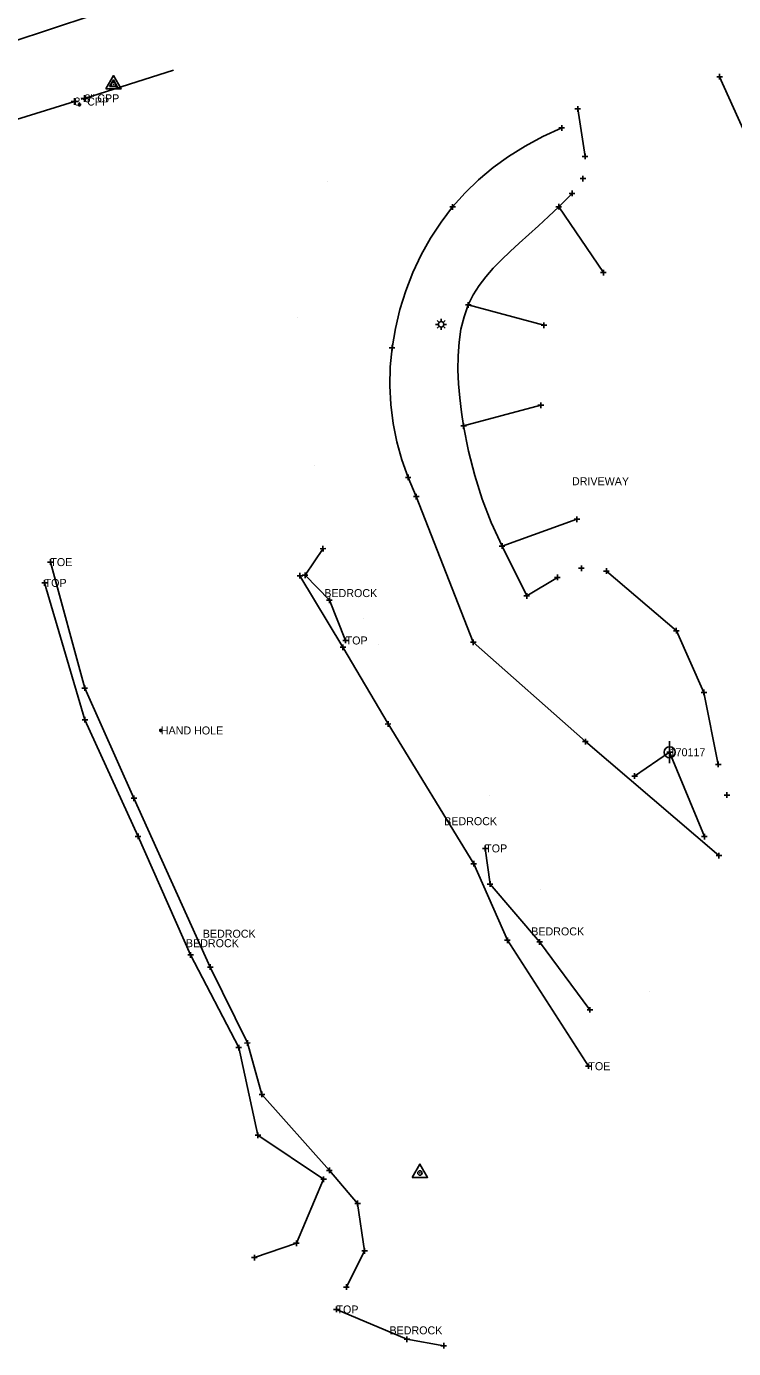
# Model space of a CAD drawing. Extents: x 1729655 to 1739338, y 463812 to 469501.
# Drawn here: x 1735905.4 to 1736064.5, y 466814.8 to 467112.2 of the extents above; entities that cross this region are included whole.
import ezdxf

# ---------------------------------------------------------------- set-up
doc = ezdxf.new("R2010")
doc.units = 0
for name, color, linetype in [('Default', 7, 'Continuous'), ('S_Bridge_Column_Round', 7, 'Continuous'), ('S_Bridge_Deck', 7, 'Continuous'), ('S_Bridge_ExpansionJoint', 7, 'Continuous'), ('S_Buildings', 7, 'Continuous'), ('S_Buildings_Steps', 7, 'Continuous'), ('S_Control_Temp_Traverse', 7, 'Continuous'), ('S_Drainage_Sump', 7, 'Continuous'), ('S_Ground_SpotElevation', 7, 'Continuous'), ('S_RetWall_Top', 7, 'Continuous'), ('S_Roadway_Bedrock_Outcrop', 7, 'Continuous'), ('S_Roadway_Drive_Gravel', 7, 'Continuous'), ('S_Survey_Shot', 7, 'Continuous'), ('S_Terrain_Boundary', 7, 'Continuous'), ('S_Terrain_High_Points', 7, 'Continuous'), ('S_Terrain_Imported_Contours', 7, 'Continuous'), ('S_Trees_TreeLine', 7, 'Continuous'), ('S_Utilities_AG_Communications', 7, 'Continuous')]:
    doc.layers.add(name, color=color, linetype=linetype)

msp = doc.modelspace()

# ---------------------------------------------------------------- linework, layer by layer
at = {"layer": 'Default'}
for p, q in [((1735973.06, 467077.39), (1735973.06, 467077.39)), ((1735966.26, 467046.77), (1735966.26, 467046.77)), ((1735970.29, 467013.47), (1735970.29, 467013.47)), ((1735981.31, 466979.09), (1735981.31, 466979.09)), ((1735984.57, 466973.07), (1735984.57, 466973.07)), ((1736009.54, 466939.2), (1736009.54, 466939.2)), ((1736021.02, 466918.08), (1736021.02, 466918.08)), ((1736045.63, 466895.05), (1736045.63, 466895.05))]:
    msp.add_line(p, q, dxfattribs=at)
at = {"layer": 'S_Bridge_Column_Round'}
for p, q in [((1736060.7, 467100.89), (1736061.97, 467100.89)), ((1736061.34, 467100.26), (1736061.33, 467101.53)), ((1736061.34, 467100.89), (1736061.34, 467100.89)), ((1736028.79, 467093.66), (1736030.07, 467093.66)), ((1736029.43, 467093.03), (1736029.43, 467094.3)), ((1736029.43, 467093.66), (1736029.43, 467093.66)), ((1736025.17, 467089.38), (1736026.44, 467089.38)), ((1736025.17, 467089.38), (1736026.44, 467089.38)), ((1736025.81, 467088.74), (1736025.81, 467090.02)), ((1736025.81, 467088.74), (1736025.81, 467090.02)), ((1736025.81, 467089.38), (1736025.81, 467089.38)), ((1736025.81, 467089.38), (1736025.81, 467089.38)), ((1736030.43, 467082.96), (1736031.71, 467082.97)), ((1736031.07, 467082.33), (1736031.07, 467083.6)), ((1736031.07, 467082.96), (1736031.07, 467082.96)), ((1736029.94, 467077.98), (1736031.21, 467077.99)), ((1736030.58, 467077.35), (1736030.57, 467078.62)), ((1736030.57, 467077.99), (1736030.57, 467077.99)), ((1736027.5, 467074.65), (1736028.77, 467074.65)), ((1736028.14, 467074.01), (1736028.14, 467075.28)), ((1736028.14, 467074.65), (1736028.14, 467074.65)), ((1736000.63, 467071.59), (1736001.9, 467071.6)), ((1736001.27, 467070.96), (1736001.27, 467072.23)), ((1736001.27, 467071.6), (1736001.27, 467071.6)), ((1736024.51, 467071.64), (1736025.78, 467071.65)), ((1736024.51, 467071.64), (1736025.78, 467071.65)), ((1736025.15, 467071.01), (1736025.14, 467072.28)), ((1736025.15, 467071.01), (1736025.14, 467072.28)), ((1736025.14, 467071.64), (1736025.14, 467071.64)), ((1736025.14, 467071.64), (1736025.14, 467071.64)), ((1736034.57, 467056.84), (1736035.84, 467056.85)), ((1736035.21, 467056.21), (1736035.21, 467057.48)), ((1736035.21, 467056.85), (1736035.21, 467056.85)), ((1736004.79, 467048.93), (1736004.79, 467050.2)), ((1736004.79, 467048.93), (1736004.79, 467050.2)), ((1736004.16, 467049.56), (1736005.43, 467049.56)), ((1736004.16, 467049.56), (1736005.43, 467049.56)), ((1736004.79, 467049.56), (1736004.79, 467049.56)), ((1736004.79, 467049.56), (1736004.79, 467049.56)), ((1736021.18, 467044.98), (1736022.45, 467044.98)), ((1736021.81, 467044.34), (1736021.81, 467045.62)), ((1736021.81, 467044.98), (1736021.81, 467044.98)), ((1735987.02, 467039.93), (1735988.29, 467039.93)), ((1735987.66, 467039.3), (1735987.65, 467040.57)), ((1735987.65, 467039.93), (1735987.65, 467039.93)), ((1736020.48, 467026.99), (1736021.76, 467026.99)), ((1736021.12, 467026.35), (1736021.12, 467027.63)), ((1736021.12, 467026.99), (1736021.12, 467026.99)), ((1736003.11, 467022.35), (1736004.38, 467022.36)), ((1736003.11, 467022.35), (1736004.38, 467022.36)), ((1736003.75, 467021.72), (1736003.74, 467022.99)), ((1736003.75, 467021.72), (1736003.74, 467022.99)), ((1736003.74, 467022.35), (1736003.74, 467022.35)), ((1736003.74, 467022.35), (1736003.74, 467022.35)), ((1735991.27, 467010.14), (1735991.27, 467011.41)), ((1735990.63, 467010.77), (1735991.9, 467010.77)), ((1735991.27, 467010.77), (1735991.27, 467010.77)), ((1735992.46, 467006.43), (1735993.73, 467006.43)), ((1735993.1, 467005.79), (1735993.1, 467007.06)), ((1735993.1, 467006.43), (1735993.1, 467006.43)), ((1736028.61, 467001.35), (1736029.88, 467001.35)), ((1736029.25, 467000.71), (1736029.25, 467001.98)), ((1736029.25, 467001.35), (1736029.25, 467001.35)), ((1735971.47, 466994.73), (1735972.74, 466994.74)), ((1735972.11, 466994.1), (1735972.1, 466995.37)), ((1735972.11, 466994.74), (1735972.11, 466994.74)), ((1736011.78, 466995.3), (1736013.05, 466995.31)), ((1736011.78, 466995.3), (1736013.05, 466995.31)), ((1736012.41, 466994.67), (1736012.41, 466995.94)), ((1736012.41, 466994.67), (1736012.41, 466995.94)), ((1736012.41, 466995.3), (1736012.41, 466995.3)), ((1736012.41, 466995.3), (1736012.41, 466995.3)), ((1735910.11, 466991.71), (1735911.38, 466991.72)), ((1735910.75, 466991.08), (1735910.75, 466992.35)), ((1735910.75, 466991.71), (1735910.75, 466991.71)), ((1736030.25, 466989.69), (1736030.24, 466990.96)), ((1735909.46, 466986.39), (1735909.45, 466987.67)), ((1735909.46, 466986.39), (1735909.45, 466987.67)), ((1735966.28, 466988.64), (1735967.55, 466988.64)), ((1735966.28, 466988.64), (1735967.55, 466988.64)), ((1735966.92, 466988.01), (1735966.91, 466989.28)), ((1735966.92, 466988.01), (1735966.91, 466989.28)), ((1735966.92, 466988.64), (1735966.92, 466988.64)), ((1735966.92, 466988.64), (1735966.92, 466988.64)), ((1735967.45, 466988.74), (1735968.72, 466988.74)), ((1735968.09, 466988.11), (1735968.08, 466989.38)), ((1735968.08, 466988.74), (1735968.08, 466988.74)), ((1736024.22, 466988.27), (1736025.5, 466988.28)), ((1736024.86, 466987.64), (1736024.86, 466988.91)), ((1736024.86, 466988.27), (1736024.86, 466988.27)), ((1736029.61, 466990.32), (1736030.88, 466990.32)), ((1736030.24, 466990.32), (1736030.24, 466990.32)), ((1736035.22, 466989.69), (1736036.49, 466989.7)), ((1736035.86, 466989.06), (1736035.86, 466990.33)), ((1736035.86, 466989.69), (1736035.86, 466989.69)), ((1735908.82, 466987.03), (1735910.09, 466987.03)), ((1735908.82, 466987.03), (1735910.09, 466987.03)), ((1735909.45, 466987.03), (1735909.45, 466987.03)), ((1735909.45, 466987.03), (1735909.45, 466987.03)), ((1736017.97, 466983.48), (1736017.96, 466984.75)), ((1735972.89, 466983.14), (1735974.17, 466983.14)), ((1735973.53, 466982.51), (1735973.53, 466983.78)), ((1735973.53, 466983.14), (1735973.53, 466983.14)), ((1736017.33, 466984.11), (1736018.6, 466984.11)), ((1736017.96, 466984.11), (1736017.96, 466984.11)), ((1736050.98, 466976.26), (1736052.25, 466976.26)), ((1736051.62, 466975.63), (1736051.61, 466976.9)), ((1736051.62, 466976.26), (1736051.62, 466976.26)), ((1735976.57, 466974.08), (1735977.84, 466974.09)), ((1735976.58, 466971.92), (1735976.58, 466973.19)), ((1735977.2, 466973.45), (1735977.2, 466974.72)), ((1735977.2, 466974.08), (1735977.2, 466974.08)), ((1736005.28, 466973.67), (1736006.55, 466973.67)), ((1736005.92, 466973.03), (1736005.91, 466974.31)), ((1736005.91, 466973.67), (1736005.91, 466973.67)), ((1735975.94, 466972.55), (1735977.22, 466972.56)), ((1735976.58, 466972.55), (1735976.58, 466972.55)), ((1735918.5, 466962.72), (1735918.5, 466963.99)), ((1735917.86, 466963.35), (1735919.14, 466963.36)), ((1735918.5, 466963.35), (1735918.5, 466963.35)), ((1736057.18, 466962.39), (1736058.45, 466962.39)), ((1736057.82, 466961.75), (1736057.81, 466963.02)), ((1736057.81, 466962.39), (1736057.81, 466962.39)), ((1735917.88, 466956.24), (1735919.15, 466956.24)), ((1735918.52, 466955.6), (1735918.52, 466956.88)), ((1735918.52, 466956.24), (1735918.52, 466956.24)), ((1735986.12, 466955.29), (1735987.39, 466955.3)), ((1735986.76, 466954.66), (1735986.76, 466955.93)), ((1735986.76, 466955.3), (1735986.76, 466955.3)), ((1736031.14, 466950.71), (1736031.14, 466951.98)), ((1736030.5, 466951.34), (1736031.77, 466951.34)), ((1736031.14, 466951.34), (1736031.14, 466951.34)), ((1736049.48, 466948.94), (1736050.75, 466948.94)), ((1736049.48, 466948.94), (1736050.75, 466948.94)), ((1736050.11, 466948.31), (1736050.11, 466949.58)), ((1736050.11, 466948.31), (1736050.11, 466949.58)), ((1736050.11, 466948.94), (1736050.11, 466948.94)), ((1736050.11, 466948.94), (1736050.11, 466948.94)), ((1736060.42, 466946.2), (1736061.69, 466946.2)), ((1736061.05, 466945.56), (1736061.05, 466946.84)), ((1736061.05, 466946.2), (1736061.05, 466946.2)), ((1736041.57, 466943.58), (1736042.85, 466943.58)), ((1736042.21, 466942.94), (1736042.21, 466944.22)), ((1736042.21, 466943.58), (1736042.21, 466943.58)), ((1735928.94, 466938.59), (1735930.21, 466938.59)), ((1735928.94, 466938.59), (1735930.21, 466938.59)), ((1735929.57, 466937.95), (1735929.57, 466939.23)), ((1735929.57, 466937.95), (1735929.57, 466939.23)), ((1735929.57, 466938.59), (1735929.57, 466938.59)), ((1735929.57, 466938.59), (1735929.57, 466938.59)), ((1736062.34, 466939.29), (1736063.62, 466939.3)), ((1736062.98, 466938.66), (1736062.98, 466939.93)), ((1736062.98, 466939.3), (1736062.98, 466939.3)), ((1735929.85, 466930), (1735931.12, 466930)), ((1735930.49, 466929.36), (1735930.48, 466930.64)), ((1735930.48, 466930), (1735930.48, 466930)), ((1736057.31, 466929.96), (1736058.58, 466929.97)), ((1736057.95, 466929.33), (1736057.94, 466930.6)), ((1736057.94, 466929.96), (1736057.94, 466929.96)), ((1736007.97, 466927.31), (1736009.24, 466927.31)), ((1736008.61, 466926.67), (1736008.6, 466927.95)), ((1736008.6, 466927.31), (1736008.6, 466927.31)), ((1736060.55, 466925.68), (1736061.82, 466925.68)), ((1736061.19, 466925.04), (1736061.18, 466926.31)), ((1736061.18, 466925.68), (1736061.18, 466925.68)), ((1736005.38, 466923.85), (1736006.66, 466923.85)), ((1736006.02, 466923.22), (1736006.02, 466924.49)), ((1736006.02, 466923.85), (1736006.02, 466923.85)), ((1736009.06, 466919.29), (1736010.33, 466919.29)), ((1736009.7, 466918.65), (1736009.7, 466919.93)), ((1736009.7, 466919.29), (1736009.7, 466919.29)), ((1736013.6, 466906.02), (1736013.59, 466907.29)), ((1736012.96, 466906.66), (1736014.23, 466906.66)), ((1736013.59, 466906.66), (1736013.59, 466906.66)), ((1736020.19, 466906.27), (1736021.46, 466906.27)), ((1736020.83, 466905.63), (1736020.82, 466906.91)), ((1736020.82, 466906.27), (1736020.82, 466906.27)), ((1735941.65, 466903.36), (1735942.93, 466903.36)), ((1735942.29, 466902.73), (1735942.29, 466904)), ((1735942.29, 466903.36), (1735942.29, 466903.36)), ((1735946.1, 466900.63), (1735947.37, 466900.63)), ((1735946.74, 466899.99), (1735946.74, 466901.27)), ((1735946.74, 466900.63), (1735946.74, 466900.63)), ((1736031.54, 466890.99), (1736032.81, 466890.99)), ((1736032.17, 466890.36), (1736032.17, 466891.63)), ((1736032.17, 466890.99), (1736032.17, 466890.99)), ((1735954.45, 466883.53), (1735955.72, 466883.54)), ((1735955.09, 466882.9), (1735955.08, 466884.17)), ((1735955.09, 466883.54), (1735955.09, 466883.54)), ((1735952.51, 466882.5), (1735953.78, 466882.5)), ((1735953.15, 466881.86), (1735953.14, 466883.14)), ((1735953.14, 466882.5), (1735953.14, 466882.5)), ((1736031.19, 466878.32), (1736032.46, 466878.33)), ((1736031.83, 466877.69), (1736031.82, 466878.96)), ((1736031.82, 466878.32), (1736031.82, 466878.32)), ((1735957.71, 466871.97), (1735958.99, 466871.97)), ((1735958.35, 466871.33), (1735958.35, 466872.6)), ((1735958.35, 466871.97), (1735958.35, 466871.97)), ((1735956.82, 466862.77), (1735958.1, 466862.77)), ((1735957.46, 466862.13), (1735957.46, 466863.41)), ((1735957.46, 466862.77), (1735957.46, 466862.77)), ((1735972.91, 466854.88), (1735974.18, 466854.88)), ((1735973.55, 466854.25), (1735973.54, 466855.52)), ((1735973.54, 466854.88), (1735973.54, 466854.88)), ((1735971.6, 466852.88), (1735972.87, 466852.88)), ((1735972.23, 466852.24), (1735972.23, 466853.51)), ((1735972.23, 466852.88), (1735972.23, 466852.88)), ((1735979.88, 466846.8), (1735979.88, 466848.07)), ((1735979.24, 466847.43), (1735980.51, 466847.44)), ((1735979.88, 466847.43), (1735979.88, 466847.43)), ((1735966.11, 466837.84), (1735966.11, 466839.11)), ((1735956.68, 466834.63), (1735956.68, 466835.9)), ((1735965.47, 466838.48), (1735966.74, 466838.48)), ((1735966.11, 466838.48), (1735966.11, 466838.48)), ((1735980.83, 466836.76), (1735982.1, 466836.76)), ((1735981.47, 466836.12), (1735981.47, 466837.4)), ((1735981.47, 466836.76), (1735981.47, 466836.76)), ((1735956.04, 466835.26), (1735957.32, 466835.27)), ((1735956.68, 466835.26), (1735956.68, 466835.26)), ((1735976.73, 466828.63), (1735978, 466828.63)), ((1735977.37, 466827.99), (1735977.36, 466829.27)), ((1735977.37, 466828.63), (1735977.37, 466828.63)), ((1735975.14, 466822.96), (1735975.14, 466824.23)), ((1735974.5, 466823.59), (1735975.77, 466823.6)), ((1735975.14, 466823.59), (1735975.14, 466823.59)), ((1735990.36, 466816.9), (1735991.63, 466816.9)), ((1735990.99, 466816.26), (1735990.99, 466817.54)), ((1735990.99, 466816.9), (1735990.99, 466816.9)), ((1735998.64, 466815.44), (1735999.92, 466815.44)), ((1735999.28, 466814.8), (1735999.28, 466816.08)), ((1735999.28, 466815.44), (1735999.28, 466815.44))]:
    msp.add_line(p, q, dxfattribs=at)
at = {"layer": 'S_Bridge_Deck'}
for p, q in [((1735998.06, 467045.19), (1735997.44, 467045.19)), ((1735998.24, 467045.63), (1735997.8, 467046.07)), ((1735998.24, 467044.75), (1735997.8, 467044.31)), ((1735998.68, 467045.82), (1735998.68, 467046.44)), ((1735998.68, 467044.57), (1735998.68, 467043.94)), ((1735999.12, 467045.63), (1735999.57, 467046.07)), ((1735999.12, 467044.75), (1735999.57, 467044.31)), ((1735999.31, 467045.19), (1735999.93, 467045.19))]:
    msp.add_line(p, q, dxfattribs=at)
msp.add_circle((1735998.68, 467045.19), 0.624, dxfattribs=at)
at = {"layer": 'S_Bridge_ExpansionJoint'}
for p, q in [((1735915.41, 467095.31), (1735916.91, 467095.31)), ((1735916.16, 467096.06), (1735916.16, 467094.56)), ((1735917.7, 467096.03), (1735919.2, 467096.03)), ((1735918.45, 467096.78), (1735918.45, 467095.28))]:
    msp.add_line(p, q, dxfattribs=at)
at = {"layer": 'S_Buildings'}
msp.add_line((1736050.11, 466951.44), (1736050.11, 466946.45), dxfattribs=at)
msp.add_circle((1736050.11, 466948.94), 1.25, dxfattribs=at)
at = {"layer": 'S_Buildings_Steps'}
for p, q in [((1735936, 466953.84), (1735935.21, 466953.84)), ((1735935.87, 466953.58), (1735935.34, 466954.11)), ((1735935.87, 466954.11), (1735935.34, 466953.58)), ((1735935.61, 466954.24), (1735935.61, 466953.45))]:
    msp.add_line(p, q, dxfattribs=at)
at = {"layer": 'S_Control_Temp_Traverse'}
for p, q in [((1735993.78, 466854.3), (1735994.03, 466854.3)), ((1735993.91, 466854.42), (1735993.91, 466854.17))]:
    msp.add_line(p, q, dxfattribs=at)
msp.add_lwpolyline([(1735992.18, 466853.3), (1735995.64, 466853.3), (1735993.91, 466856.29)], close=True, dxfattribs=at)
msp.add_circle((1735993.91, 466854.3), 0.499, dxfattribs=at)
at = {"layer": 'S_Drainage_Sump'}
for p, q in [((1735917.7, 467094.61), (1735916.91, 467094.61)), ((1735917.57, 467094.34), (1735917.04, 467094.87)), ((1735917.57, 467094.87), (1735917.04, 467094.34)), ((1735917.3, 467095), (1735917.3, 467094.21))]:
    msp.add_line(p, q, dxfattribs=at)
at = {"layer": 'S_Ground_SpotElevation'}
for p, q in [((1736061.34, 467100.89), (1736070.1, 467081.48)), ((1736031.07, 467082.96), (1736029.43, 467093.66)), ((1736025.14, 467071.64), (1736028.14, 467074.65)), ((1736017.96, 466984.11), (1736012.41, 466995.3)), ((1736024.86, 466988.27), (1736017.96, 466984.11)), ((1736051.62, 466976.26), (1736035.86, 466989.69)), ((1736057.81, 466962.39), (1736051.62, 466976.26)), ((1736061.05, 466946.2), (1736057.81, 466962.39))]:
    msp.add_line(p, q, dxfattribs=at)
msp.add_lwpolyline([(1736012.41, 466995.3), (1736009.98, 467000.6), (1736007.93, 467005.88), (1736006.24, 467011.22), (1736004.85, 467016.69), (1736003.74, 467022.35), (1736003.26, 467025.47), (1736002.86, 467028.64), (1736002.59, 467031.82), (1736002.45, 467034.98), (1736002.49, 467038.1), (1736002.71, 467041.15), (1736003.15, 467044.1), (1736003.84, 467046.91), (1736004.79, 467049.56), (1736005.89, 467051.8), (1736007.21, 467053.9), (1736008.73, 467055.9), (1736010.41, 467057.83), (1736012.24, 467059.72), (1736014.2, 467061.58), (1736016.27, 467063.46), (1736018.42, 467065.38), (1736020.63, 467067.36), (1736022.88, 467069.44), (1736025.14, 467071.64)], dxfattribs=at)
at = {"layer": 'S_RetWall_Top'}
for p, q in [((1735938.48, 467102.34), (1735918.45, 467096.03)), ((1735916.16, 467095.31), (1735703.48, 467030.18))]:
    msp.add_line(p, q, dxfattribs=at)
at = {"layer": 'S_Roadway_Bedrock_Outcrop'}
for points in [[(1735977.2, 466974.08), (1735973.53, 466983.14), (1735968.08, 466988.74), (1735972.11, 466994.74)], [(1735910.75, 466991.71), (1735918.5, 466963.35), (1735929.57, 466938.59), (1735946.74, 466900.63), (1735955.09, 466883.54), (1735958.35, 466871.97), (1735973.54, 466854.88), (1735979.88, 466847.43), (1735981.47, 466836.76), (1735977.37, 466828.63)], [(1736031.82, 466878.32), (1736013.59, 466906.66), (1736006.02, 466923.85), (1735986.76, 466955.3), (1735976.58, 466972.55), (1735966.92, 466988.64)], [(1735909.45, 466987.03), (1735918.52, 466956.24), (1735930.48, 466930), (1735942.29, 466903.36), (1735953.14, 466882.5), (1735957.46, 466862.77), (1735972.23, 466852.88), (1735966.11, 466838.48), (1735956.68, 466835.26)], [(1736008.6, 466927.31), (1736009.7, 466919.29), (1736020.82, 466906.27), (1736032.17, 466890.99)], [(1735975.14, 466823.59), (1735990.99, 466816.9), (1735999.28, 466815.44)]]:
    msp.add_lwpolyline(points, dxfattribs=at)
at = {"layer": 'S_Roadway_Drive_Gravel'}
for points in [[(1736035.21, 467056.85), (1736025.14, 467071.64)], [(1736004.79, 467049.56), (1736021.81, 467044.98)], [(1736021.12, 467026.99), (1736003.74, 467022.35)], [(1736012.41, 466995.3), (1736029.25, 467001.35)]]:
    msp.add_lwpolyline(points, dxfattribs=at)
at = {"layer": 'S_Survey_Shot'}
msp.add_lwpolyline([(1735327.94, 466925.11), (1735706.87, 467043.8), (1735777.22, 467067.85), (1735856.5, 467093.65), (1735947.31, 467123.71), (1736072.24, 467163.39), (1736148.46, 467186.6), (1736188.58, 467199.8), (1736250.41, 467218.61), (1736341.55, 467246.49), (1736425.62, 467273.68), (1736484.8, 467292.24), (1736522.29, 467304.69), (1736527.82, 467289.35)], dxfattribs=at)
at = {"layer": 'S_Terrain_Boundary'}
for p, q in [((1735924.8, 467099.16), (1735925.05, 467099.16)), ((1735924.93, 467099.29), (1735924.93, 467099.04))]:
    msp.add_line(p, q, dxfattribs=at)
msp.add_lwpolyline([(1735923.2, 467098.16), (1735926.66, 467098.16), (1735924.93, 467101.16)], close=True, dxfattribs=at)
msp.add_circle((1735924.93, 467099.16), 0.499, dxfattribs=at)
at = {"layer": 'S_Terrain_Imported_Contours'}
msp.add_line((1735924.93, 467099.16), (1735924.93, 467099.16), dxfattribs=at)
msp.add_lwpolyline([(1735924.06, 467098.66), (1735924.93, 467100.16), (1735925.8, 467098.66)], close=True, dxfattribs=at)
msp.add_circle((1735924.93, 467099.16), 0.5, dxfattribs=at)
at = {"layer": 'S_Trees_TreeLine'}
for p, q in [((1735993.1, 467006.43), (1736005.91, 466973.67)), ((1736005.91, 466973.67), (1736031.14, 466951.34)), ((1736031.14, 466951.34), (1736061.18, 466925.68))]:
    msp.add_line(p, q, dxfattribs=at)
msp.add_lwpolyline([(1736025.81, 467089.38), (1736021.59, 467087.43), (1736017.61, 467085.29), (1736013.88, 467082.97), (1736010.39, 467080.45), (1736007.12, 467077.72), (1736004.08, 467074.77), (1736001.27, 467071.6), (1735998.68, 467068.2), (1735996.32, 467064.6), (1735994.2, 467060.8), (1735992.33, 467056.85), (1735990.73, 467052.76), (1735989.41, 467048.56), (1735988.38, 467044.28), (1735987.65, 467039.93), (1735987.25, 467035.67), (1735987.16, 467031.39), (1735987.37, 467027.14), (1735987.88, 467022.92), (1735988.7, 467018.77), (1735989.83, 467014.71), (1735991.27, 467010.77), (1735991.88, 467009.33), (1735992.5, 467007.89), (1735993.1, 467006.43)], dxfattribs=at)
at = {"layer": 'S_Utilities_AG_Communications'}
for points in [[(1736042.21, 466943.58), (1736050.11, 466948.94)], [(1736057.94, 466929.96), (1736050.11, 466948.94)]]:
    msp.add_lwpolyline(points, dxfattribs=at)

# ---------------------------------------------------------------- texts
at = {"layer": 'S_Terrain_High_Points'}
for s, p in [('8" CPP', (1735916.16, 467094.41)), ('8" CPP', (1735918.45, 467095.13)), ('DRIVEWAY', (1736028.13, 467009)), ('TOE', (1735910.75, 466990.81)), ('TOP', (1735909.45, 466986.13)), ('TOP', (1735909.45, 466986.13)), ('BEDROCK', (1735972.4, 466983.84)), ('TOP', (1735977.2, 466973.18)), ('HAND HOLE', (1735935.61, 466952.94)), ('170117', (1736050.11, 466948.04)), ('170117', (1736050.11, 466948.04)), ('170117', (1736050.11, 466948.04)), ('BEDROCK', (1735999.37, 466932.53)), ('TOP', (1736008.6, 466926.41)), ('BEDROCK', (1735945.05, 466907.22)), ('BEDROCK', (1736018.96, 466907.74)), ('BEDROCK', (1735941.26, 466905.09)), ('TOE', (1736031.82, 466877.42)), ('TOP', (1735975.14, 466822.69)), ('BEDROCK', (1735987.06, 466818))]:
    msp.add_text(s, height=1.8, dxfattribs=at).set_placement(p)

doc.saveas('drawing.dxf')
